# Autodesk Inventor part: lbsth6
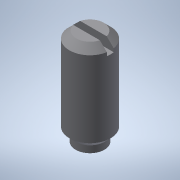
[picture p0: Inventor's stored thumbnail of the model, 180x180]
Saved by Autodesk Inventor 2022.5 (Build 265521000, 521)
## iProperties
Created: 2016-12
Part Number: lbsth6
Material: 一般
Document SubType Name: Modeling
Designer: imaocorp
Density: 1 g/cm^3
Appearance: 既定
Author: imaocorp
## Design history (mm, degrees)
node "lbsth6.x_t1"
node "lbsth6"
node "Base1"
